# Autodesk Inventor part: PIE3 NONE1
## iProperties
Shininess: 64.0
Length Units: 11269
Angle Units: 11279
Time Units: 11290
Mass Units: 11286
Length Display Precision: 3
Angle Display Precision: 2
Compacted: True
Part Number: PIE3 NONE1
Document SubType Name: Modeling
Created: 2004-08
Designer: John Blackburn
Manufacturer: Standard
Standards Organization: Custom
Density: 0.0
Volumn: 0.0
Area: 0.0
PropertySet Name: Model Information
Control State: 0
Master: False
Checked Out: False
Author: John Blackburn
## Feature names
1. Erst1
